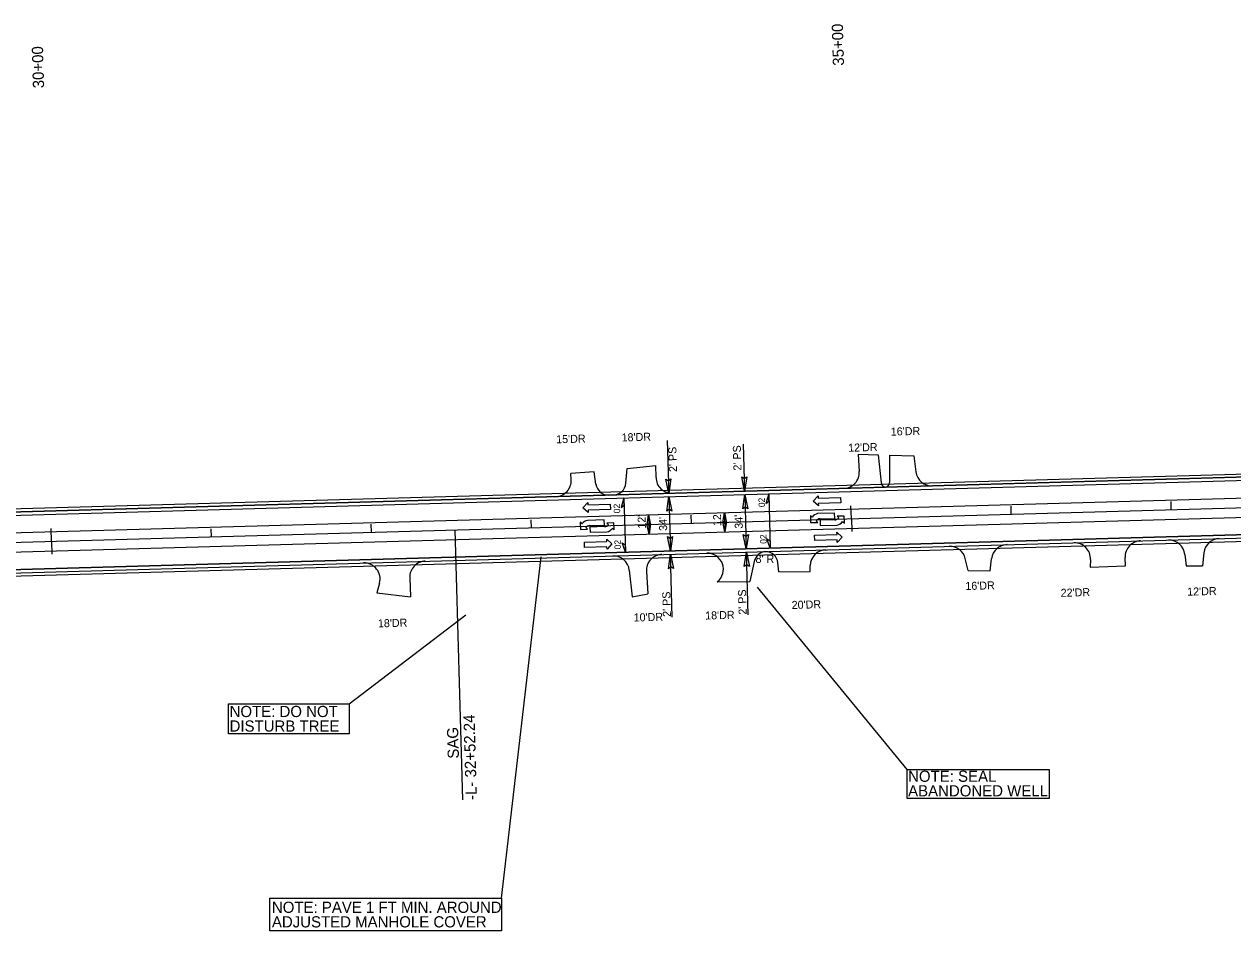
# Model space of a CAD drawing. Extents: x 1755545 to 1761252, y 736169 to 737766.
# Drawn here: x 1757667 to 1758422, y 736739 to 737306 of the extents above; entities that cross this region are included whole.
import ezdxf

# ---------------------------------------------------------------- set-up
doc = ezdxf.new("R2010")
doc.units = 0
for name, color, linetype in [('Exist Contamination Potential Cell', 7, 'Continuous'), ('Exist Cultural Church Label', 7, 'Continuous'), ('Old_Level_1', 7, 'Continuous'), ('Old_Level_15', 7, 'Continuous'), ('Prop Dimension', 7, 'Continuous'), ('Prop Horizontal Alignment', 7, 'Continuous'), ('Prop Horizontal Alignment Tick Label', 7, 'Continuous'), ('Prop Horizontal Alignment Tick Large', 7, 'Continuous'), ('Prop Horizontal Alignment Tick Small', 7, 'Continuous'), ('Prop Lane Arrow CELL', 7, 'Continuous'), ('Prop Lane Lines', 7, 'Continuous'), ('Prop Paved Shoulder', 7, 'Continuous'), ('Prop Shade Light', 7, 'Continuous'), ('Prop Superelevation Label', 7, 'Continuous'), ('Prop Terminator CELL', 7, 'Continuous'), ('Scratch_Level_4', 7, 'Continuous'), ('Scratch_Level_6', 7, 'Continuous')]:
    doc.layers.add(name, color=color, linetype=linetype)

msp = doc.modelspace()

# ---------------------------------------------------------------- linework, layer by layer
at = {"layer": 'Exist Contamination Potential Cell'}
for p, q in [((1757498.66, 736960.29), (1760222.11, 737037.63)), ((1757497.77, 736994.28), (1758821.01, 737031.85))]:
    msp.add_line(p, q, dxfattribs=at)
at = {"layer": 'Exist Cultural Church Label'}
for points in [[(1758131.93, 737012.29), (1758130.11, 737006.23), (1758132.07, 737007.66)], [(1758041.48, 737009.72), (1758039.65, 737003.66), (1758041.61, 737005.1)], [(1758042.44, 736975.73), (1758040.27, 736981.67), (1758042.31, 736980.36)], [(1758132.9, 736978.3), (1758130.73, 736984.24), (1758132.77, 736982.92)]]:
    msp.add_lwpolyline(points, close=True, dxfattribs=at)
at = {"layer": 'Old_Level_1'}
for p, q in [((1758187.88, 737037.04), (1758200.4, 737036.67)), ((1758187.88, 737037.04), (1758188.48, 737026.17)), ((1758200.4, 737036.67), (1758202.22, 737019.06)), ((1758207.31, 737036.46), (1758207.3, 737019.34)), ((1758207.31, 737036.46), (1758222.58, 737036)), ((1758222.58, 737036), (1758223.87, 737025.92)), ((1758042.67, 737018.89), (1758043.41, 737028.03)), ((1758043.41, 737028.03), (1758061.48, 737029.99)), ((1758061.5, 737022.55), (1758061.48, 737029.99)), ((1758022.92, 737026.08), (1758008.24, 737024.94)), ((1758008.49, 737021.17), (1758008.24, 737024.94)), ((1758023.94, 737018.39), (1758022.92, 737026.08)), ((1758391.95, 736974.35), (1758392.64, 736967.29)), ((1758403.78, 736975.4), (1758402.86, 736967.37)), ((1758122.86, 736970.01), (1758120.01, 736957.5)), ((1758138.28, 736963.53), (1758137.64, 736969.12)), ((1758157.84, 736963.82), (1758157.89, 736967.42)), ((1758256.62, 736964.27), (1758254.72, 736971.9)), ((1758270.32, 736964.24), (1758271.19, 736971.68)), ((1758332.96, 736971.29), (1758332.77, 736966.45)), ((1758332.77, 736966.45), (1758354.82, 736967.31)), ((1758354.82, 736967.31), (1758354.6, 736972.45)), ((1758392.64, 736967.29), (1758402.86, 736967.37)), ((1757907.61, 736959.88), (1757908.04, 736947.89)), ((1758044.82, 736964.51), (1758046.49, 736947.91)), ((1758055.51, 736963.7), (1758056.45, 736949.89)), ((1758138.28, 736963.53), (1758157.84, 736963.82)), ((1758256.62, 736964.27), (1758270.32, 736964.24)), ((1757888.74, 736956.49), (1757887.12, 736950.47)), ((1758099.61, 736957.2), (1758120.01, 736957.5)), ((1758099.61, 736957.2), (1758099.75, 736957.31)), ((1757887.12, 736950.47), (1757908.04, 736947.89)), ((1758046.49, 736947.91), (1758056.45, 736949.89))]:
    msp.add_line(p, q, dxfattribs=at)
for centre, radius, start, end in [((1757998.51, 737020.5), 10, 271.62654, 3.81473), ((1758034.7, 737019.53), 8, 271.62654, 355.39731), ((1758071.5, 737022.58), 10, 180.17711, 271.62654), ((1758178.5, 737025.62), 10, 271.62654, 3.20631), ((1758205.2, 737019.37), 3, 185.90278, 271.62654), ((1758204.3, 737019.34), 3, 271.62654, 359.97376), ((1758233.79, 737027.19), 10, 187.27482, 271.62654), ((1758031.87, 737019.45), 8, 187.59393, 271.62654), ((1758322.97, 736971.69), 10, 357.68981, 91.62654), ((1758364.59, 736972.88), 10, 91.62654, 182.44905), ((1758381.99, 736973.37), 10, 5.62164, 91.62654), ((1758413.71, 736974.27), 10, 91.62654, 173.49742), ((1758034.87, 736963.51), 10, 5.74636, 91.62654), ((1758065.49, 736964.38), 10, 91.62654, 183.88848), ((1758093.58, 736965.18), 10, 308.06435, 91.62654), ((1758130.66, 736968.23), 8, 95.10891, 167.1589), ((1758129.69, 736968.21), 8, 6.53741, 88.14416), ((1758167.89, 736967.29), 10, 91.62654, 179.23874), ((1758245.02, 736969.48), 10, 13.98779, 91.62654), ((1758281.12, 736970.51), 10, 91.62654, 173.27778), ((1757879.08, 736959.09), 10, 344.93882, 91.62654), ((1757917.6, 736960.18), 10, 91.62654, 181.71027)]:
    msp.add_arc(centre, radius, start, end, dxfattribs=at)
at = {"layer": 'Old_Level_15'}
msp.add_line((1757935.88, 736989.71), (1757940.67, 736821.02), dxfattribs=at)
at = {"layer": 'Prop Dimension'}
for p, q in [((1758068.54, 737045.49), (1758069.47, 737012.52)), ((1758116.05, 737043.33), (1758116.88, 737013.86)), ((1758116.94, 737011.86), (1758117.91, 736977.88)), ((1758069.53, 737010.52), (1758070.49, 736976.53)), ((1758056.78, 736999.15), (1758057.12, 736987.15)), ((1758104.19, 737000.5), (1758104.54, 736988.5)), ((1758071.67, 736935.11), (1758070.55, 736974.53)), ((1758119.08, 736936.64), (1758117.96, 736975.88)), ((1757964.9, 736759.65), (1757989.72, 736972.88)), ((1758218.43, 736840.13), (1758124.9, 736954)), ((1757869.74, 736881.11), (1757942.75, 736936.67))]:
    msp.add_line(p, q, dxfattribs=at)
for points in [[(1757794.46, 736881.11), (1757869.74, 736881.11), (1757869.74, 736862.36), (1757794.46, 736862.36)], [(1758218.43, 736840.13), (1758307.11, 736840.13), (1758307.11, 736821.87), (1758218.43, 736821.87)], [(1757820.15, 736759.65), (1757964.9, 736759.65), (1757964.9, 736739.26), (1757820.15, 736739.26)]]:
    msp.add_lwpolyline(points, close=True, dxfattribs=at)
at = {"layer": 'Prop Horizontal Alignment'}
msp.add_line((1757285.64, 736971.25), (1760282.69, 737056.35), dxfattribs=at)
at = {"layer": 'Prop Horizontal Alignment Tick Large'}
for p, q in [((1758183.54, 736996.75), (1758183.31, 737004.74)), ((1758183.54, 736996.75), (1758183.76, 736988.75)), ((1757683.74, 736982.55), (1757683.51, 736990.55)), ((1757683.74, 736982.55), (1757683.96, 736974.56))]:
    msp.add_line(p, q, dxfattribs=at)
at = {"layer": 'Prop Horizontal Alignment Tick Small'}
for p, q in [((1758283.5, 736999.58), (1758283.35, 737004.58)), ((1758383.46, 737002.42), (1758383.31, 737007.42)), ((1758083.58, 736993.91), (1758083.43, 736998.91)), ((1757783.7, 736985.39), (1757783.55, 736990.39)), ((1757883.66, 736988.23), (1757883.51, 736993.23)), ((1757983.62, 736991.07), (1757983.47, 736996.07))]:
    msp.add_line(p, q, dxfattribs=at)
at = {"layer": 'Prop Lane Arrow CELL'}
for p, q in [((1758015.85, 737003.52), (1758018.91, 737006.81)), ((1758018.91, 737006.81), (1758018.95, 737005.31)), ((1758018.95, 737005.31), (1758032.95, 737005.71)), ((1758032.95, 737005.71), (1758033.04, 737002.41)), ((1758159.71, 737007.77), (1758162.77, 737011.06)), ((1758162.95, 737004.76), (1758159.71, 737007.77)), ((1758162.77, 737011.06), (1758162.81, 737009.56)), ((1758162.81, 737009.56), (1758176.81, 737009.96)), ((1758176.9, 737006.66), (1758162.91, 737006.26)), ((1758162.91, 737006.26), (1758162.95, 737004.76)), ((1758176.81, 737009.96), (1758176.9, 737006.66)), ((1758019.09, 737000.51), (1758015.85, 737003.52)), ((1758033.04, 737002.41), (1758019.05, 737002.01)), ((1758019.05, 737002.01), (1758019.09, 737000.51)), ((1758159.11, 736997.73), (1758157.98, 736998.75)), ((1758157.98, 736998.75), (1758158.11, 736994.3)), ((1758173.04, 737000.23), (1758162.5, 736999.93)), ((1758163.99, 736996.67), (1758173.14, 736996.93)), ((1758173.14, 736996.93), (1758173.04, 737000.23)), ((1758179.1, 736998.35), (1758174.6, 736998.27)), ((1758174.6, 736998.27), (1758175.68, 736997.25)), ((1758179.17, 736993.95), (1758179.1, 736998.35)), ((1758015.25, 736993.48), (1758014.12, 736994.5)), ((1758014.12, 736994.5), (1758014.25, 736990.05)), ((1758014.25, 736990.05), (1758018.75, 736990.18)), ((1758018.75, 736990.18), (1758017.67, 736991.2)), ((1758029.19, 736995.98), (1758018.64, 736995.68)), ((1758020.13, 736992.42), (1758029.28, 736992.68)), ((1758029.35, 736991.78), (1758020.21, 736991.52)), ((1758020.21, 736991.52), (1758020.3, 736988.22)), ((1758029.28, 736992.68), (1758029.19, 736995.98)), ((1758035.24, 736994.1), (1758030.74, 736994.02)), ((1758030.74, 736994.02), (1758031.82, 736993)), ((1758034.24, 736990.72), (1758035.32, 736989.7)), ((1758035.32, 736989.7), (1758035.24, 736994.1)), ((1758158.11, 736994.3), (1758162.6, 736994.43)), ((1758162.6, 736994.43), (1758161.52, 736995.45)), ((1758173.21, 736996.03), (1758164.07, 736995.77)), ((1758164.07, 736995.77), (1758164.16, 736992.47)), ((1758164.16, 736992.47), (1758174.71, 736992.77)), ((1758178.09, 736994.97), (1758179.17, 736993.95)), ((1758016.74, 736982.1), (1758030.73, 736982.49)), ((1758016.83, 736978.8), (1758016.74, 736982.1)), ((1758020.3, 736988.22), (1758030.85, 736988.52)), ((1758030.73, 736982.49), (1758030.69, 736983.99)), ((1758030.69, 736983.99), (1758033.93, 736980.99)), ((1758160.6, 736986.35), (1758174.59, 736986.75)), ((1758160.69, 736983.05), (1758160.6, 736986.35)), ((1758174.69, 736983.45), (1758160.69, 736983.05)), ((1758174.59, 736986.75), (1758174.55, 736988.25)), ((1758174.55, 736988.25), (1758177.79, 736985.24)), ((1758174.73, 736981.95), (1758174.69, 736983.45)), ((1758177.79, 736985.24), (1758174.73, 736981.95)), ((1758030.83, 736979.2), (1758016.83, 736978.8)), ((1758030.87, 736977.7), (1758030.83, 736979.2)), ((1758033.93, 736980.99), (1758030.87, 736977.7))]:
    msp.add_line(p, q, dxfattribs=at)
for centre, radius, start, end in [((1758163.42, 736994.75), 5.25, 100.30261, 145.6143), ((1758164.06, 736993.38), 3.28, 91.62654, 141.28471), ((1758173.13, 736999.29), 3.28, 271.62654, 321.28471), ((1758019.57, 736990.5), 5.25, 100.30261, 145.6143), ((1758020.2, 736989.13), 3.28, 91.62654, 141.28471), ((1758029.27, 736995.04), 3.28, 271.62654, 321.28471), ((1758029.91, 736993.67), 5.25, 280.30261, 325.6143), ((1758173.77, 736997.92), 5.25, 280.30261, 325.6143)]:
    msp.add_arc(centre, radius, start, end, dxfattribs=at)
at = {"layer": 'Prop Lane Lines'}
for p, q in [((1757285.47, 736977.25), (1760207.53, 737060.22)), ((1757285.81, 736965.25), (1760207.87, 737048.23))]:
    msp.add_line(p, q, dxfattribs=at)
at = {"layer": 'Prop Paved Shoulder'}
for p, q in [((1757497.71, 736996.28), (1758820.95, 737033.85)), ((1757498.72, 736958.29), (1758854.08, 736996.78))]:
    msp.add_line(p, q, dxfattribs=at)
at = {"layer": 'Prop Shade Light'}
for p, q in [((1760222.11, 737037.63), (1757498.66, 736960.29)), ((1758820.95, 737033.85), (1757497.71, 736996.28)), ((1757497.77, 736994.28), (1758821.01, 737031.85)), ((1757498.72, 736958.29), (1758862.05, 736997.01))]:
    msp.add_line(p, q, dxfattribs=at)
at = {"layer": 'Prop Superelevation Label'}
for p, q in [((1758131.93, 737012.29), (1758132.9, 736978.3)), ((1758041.48, 737009.72), (1758042.44, 736975.73))]:
    msp.add_line(p, q, dxfattribs=at)
at = {"layer": 'Prop Terminator CELL'}
for points in [[(1758070.77, 737021.56), (1758069.47, 737012.52), (1758067.62, 737021.52), (1758069.25, 737020.41)], [(1758118.18, 737022.9), (1758116.88, 737013.86), (1758115.03, 737022.86), (1758116.66, 737021.76)], [(1758115.65, 737002.82), (1758116.94, 737011.86), (1758118.8, 737002.86), (1758117.17, 737003.97)], [(1758068.24, 737001.48), (1758069.53, 737010.52), (1758071.39, 737001.51), (1758069.75, 737002.62)], [(1758055.88, 736992.82), (1758056.78, 736999.15), (1758058.08, 736992.85), (1758056.94, 736993.62)], [(1758103.29, 736994.17), (1758104.19, 737000.5), (1758105.49, 736994.2), (1758104.35, 736994.97)], [(1758058.03, 736993.48), (1758057.12, 736987.15), (1758055.82, 736993.46), (1758056.97, 736992.68)], [(1758105.44, 736994.83), (1758104.54, 736988.5), (1758103.24, 736994.8), (1758104.38, 736994.03)], [(1758071.79, 736985.57), (1758070.49, 736976.53), (1758068.64, 736985.53), (1758070.27, 736984.43)], [(1758119.2, 736986.92), (1758117.91, 736977.88), (1758116.05, 736986.88), (1758117.68, 736985.77)], [(1758069.26, 736965.49), (1758070.55, 736974.53), (1758072.41, 736965.53), (1758070.78, 736966.63)], [(1758116.67, 736966.84), (1758117.96, 736975.88), (1758119.82, 736966.88), (1758118.19, 736967.98)]]:
    msp.add_lwpolyline(points, close=True, dxfattribs=at)
at = {"layer": 'Scratch_Level_6'}
for p, q in [((1757497.65, 736998.28), (1758820.89, 737035.85)), ((1757498.78, 736956.29), (1758854.11, 736994.78))]:
    msp.add_line(p, q, dxfattribs=at)

# ---------------------------------------------------------------- texts
at = {"layer": 'Old_Level_15'}
for s, p in [('-L- 32+52.24', (1757949.63, 736821.15)), ('SAG', (1757938.39, 736846.91))]:
    msp.add_text(s, height=7, rotation=91.62654, dxfattribs=at).set_placement(p)
at = {"layer": 'Prop Dimension'}
for s, rotation, p in [("2' PS", 91.62654, (1758114.91, 737026.87)), ("2' PS", 91.62654, (1758074.62, 737025.97)), ("12'", 91.62654, (1758055.18, 736990.58)), ("34'", 91.62654, (1758068.49, 736989.19)), ("12'", 91.62654, (1758102.3, 736992.16)), ("34'", 91.62654, (1758115.75, 736990.54)), ("8' R", 360, (1758123.67, 736969.11)), ("2' PS", 91.62654, (1758070.82, 736935.5)), ("2' PS", 91.62654, (1758118.14, 736936.84))]:
    msp.add_text(s, height=5, rotation=rotation, dxfattribs=at).set_placement(p)
for s, p in [('NOTE: DO NOT ', (1757795.05, 736872.8)), ('DISTURB TREE', (1757795.05, 736863.7)), ('NOTE: SEAL ', (1758219.01, 736832.34)), ('ABANDONED WELL', (1758219.01, 736823.24)), ('NOTE: PAVE 1 FT MIN. AROUND ', (1757821.5, 736750.48)), ('ADJUSTED MANHOLE COVER', (1757821.5, 736741.38))]:
    msp.add_text(s, height=7, dxfattribs=at).set_placement(p)
at = {"layer": 'Prop Horizontal Alignment Tick Label'}
for s, p in [('35+00', (1758179, 737279.8)), ('30+00', (1757679.19, 737265.71))]:
    msp.add_text(s, height=7, rotation=91.62654, dxfattribs=at).set_placement(p)
at = {"layer": 'Prop Superelevation Label'}
for p in [(1758039.14, 737000.15), (1758129.63, 737003.97), (1758039.59, 736977.6), (1758130.64, 736981.07)]:
    msp.add_text('02', height=4, rotation=91.62654, dxfattribs=at).set_placement(p)
at = {"layer": 'Scratch_Level_4'}
for s, p in [("15'DR", (1757999.2, 737043.82)), ("18'DR", (1758040.06, 737044.96)), ("16'DR", (1758208.24, 737048.61)), ("12'DR", (1758181.62, 737038.52)), ("16'DR", (1758254.84, 736952.15)), ("22'DR", (1758314.41, 736947.89)), ("12'DR", (1758393.46, 736948.62)), ("20'DR", (1758146.32, 736940.31)), ("10'DR", (1758047.6, 736932.47)), ("18'DR", (1758092.29, 736933.72)), ("18'DR", (1757887.81, 736928.8))]:
    msp.add_text(s, height=5, rotation=1.62654, dxfattribs=at).set_placement(p)

doc.saveas('drawing.dxf')
